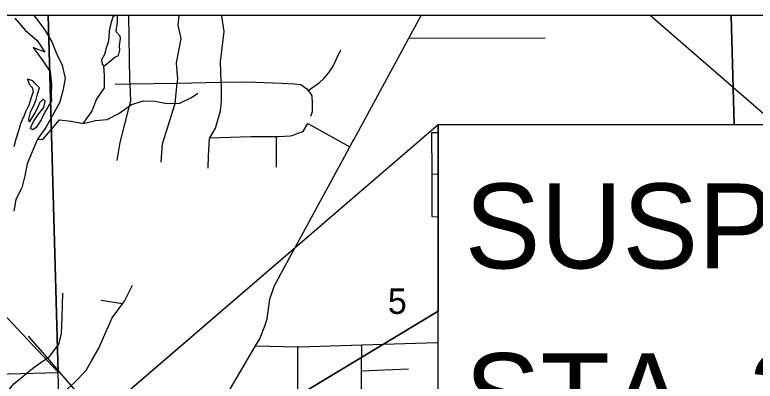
# Model space of a CAD drawing. Extents: x -37878.7 to -37844.7, y -19791.4 to -19769.4.
# Drawn here: x -37872.242 to -37871.021, y -19774.693 to -19774.089 of the extents above; entities that cross this region are included whole.
import ezdxf

# ---------------------------------------------------------------- set-up
doc = ezdxf.new("R2010")
doc.units = 0
for name, color, linetype in [('GM_X_City_Street', 7, 'Continuous'), ('GM_X_Major_River', 7, 'Continuous'), ('GM_X_Minor_Lake', 7, 'Continuous'), ('GM_X_Minor_River', 7, 'Continuous'), ('GM_X_Section', 7, 'Continuous'), ('GM_X_Section_Text', 7, 'Continuous'), ('GM_X_State_Route', 7, 'Continuous'), ('GM_X_US_Route', 7, 'Continuous'), ('TX_P_1', 7, 'Continuous')]:
    doc.layers.add(name, color=color, linetype=linetype)

msp = doc.modelspace()

# ---------------------------------------------------------------- linework, layer by layer
at = {"layer": 'GM_X_City_Street'}
for points in [[(-37872.0728, -19774.3288), (-37872.0683, -19774.299), (-37872.0607, -19774.2691), (-37872.0534, -19774.2411), (-37872.0504, -19774.2308), (-37872.0518, -19774.2025), (-37872.0521, -19774.1967), (-37872.0539, -19774.0898)], [(-37872.0003, -19774.3317), (-37871.9984, -19774.3013), (-37871.9774, -19774.2348), (-37871.9739, -19774.2012), (-37871.9733, -19774.1948), (-37871.975, -19774.1679), (-37871.9678, -19774.1279), (-37871.9726, -19774.1056), (-37871.9709, -19774.0898)], [(-37871.9228, -19774.3418), (-37871.9223, -19774.3213), (-37871.9209, -19774.2931), (-37871.9201, -19774.2917), (-37871.9108, -19774.2757), (-37871.9026, -19774.247), (-37871.9011, -19774.2317), (-37871.9012, -19774.2044), (-37871.9014, -19774.2), (-37871.9027, -19774.166), (-37871.8969, -19774.1161), (-37871.9004, -19774.0907), (-37871.9002, -19774.0898)], [(-37871.592, -19774.127), (-37871.3671, -19774.1266)], [(-37871.7581, -19774.2135), (-37871.7396, -19774.2001), (-37871.7318, -19774.1934), (-37871.7234, -19774.1833), (-37871.7169, -19774.1736), (-37871.7112, -19774.1613), (-37871.704, -19774.1462)], [(-37872.0763, -19774.2029), (-37872.0518, -19774.2025), (-37871.9739, -19774.2012), (-37871.9014, -19774.2), (-37871.8593, -19774.1993), (-37871.802, -19774.2013), (-37871.7804, -19774.2025), (-37871.7701, -19774.2034), (-37871.7601, -19774.2107), (-37871.7581, -19774.2135), (-37871.7539, -19774.2197)], [(-37871.7539, -19774.2197), (-37871.7522, -19774.2222), (-37871.7514, -19774.2351), (-37871.7517, -19774.2484), (-37871.7542, -19774.2561)], [(-37871.8164, -19774.2895), (-37871.816, -19774.2895), (-37871.8104, -19774.2896), (-37871.8077, -19774.2896), (-37871.7873, -19774.2882), (-37871.7831, -19774.2871), (-37871.7717, -19774.2829), (-37871.7681, -19774.2814), (-37871.766, -19774.28), (-37871.7587, -19774.268), (-37871.6894, -19774.3064)], [(-37871.9201, -19774.2917), (-37871.8524, -19774.2891), (-37871.8164, -19774.2895)], [(-37871.8104, -19774.3402), (-37871.8104, -19774.2896)], [(-37871.5548, -19774.283), (-37871.544, -19774.2828)], [(-37871.5548, -19774.283), (-37871.5544, -19774.3513), (-37871.5541, -19774.4216), (-37871.544, -19774.4217)], [(-37871.5544, -19774.3513), (-37871.544, -19774.3511)], [(-37872.1159, -19774.6604), (-37872.1039, -19774.6394), (-37872.0815, -19774.5884), (-37872.0642, -19774.5654), (-37872.061, -19774.5611), (-37872.048, -19774.5344)], [(-37872.3287, -19774.8159), (-37872.3022, -19774.7677), (-37872.2433, -19774.6974), (-37872.2097, -19774.6698), (-37872.1882, -19774.6547), (-37872.1847, -19774.6522), (-37872.1692, -19774.6318), (-37872.1649, -19774.615), (-37872.1639, -19774.5876), (-37872.1628, -19774.5477)], [(-37872.0642, -19774.5654), (-37872.0997, -19774.5598)], [(-37872.092, -19774.7656), (-37872.0938, -19774.7635), (-37872.1055, -19774.7499), (-37872.1489, -19774.7001), (-37872.1882, -19774.6547), (-37872.2195, -19774.6187)], [(-37871.8448, -19774.6347), (-37871.7749, -19774.6363), (-37871.7731, -19774.6364), (-37871.6698, -19774.633), (-37871.5455, -19774.6291), (-37871.5434, -19774.629)], [(-37871.6552, -19775.4518), (-37871.6539, -19775.3706), (-37871.6549, -19775.3071), (-37871.6549, -19775.2283), (-37871.6728, -19775.1244), (-37871.6721, -19775.0128), (-37871.6706, -19774.7769), (-37871.6703, -19774.7245), (-37871.67, -19774.6758), (-37871.6698, -19774.633)], [(-37871.7783, -19775.1244), (-37871.7783, -19775.1232), (-37871.7775, -19775.0138), (-37871.7769, -19774.9281), (-37871.7753, -19774.6945), (-37871.7749, -19774.6363)], [(-37872.2751, -19774.8469), (-37872.2473, -19774.8077), (-37872.209, -19774.7565), (-37872.1695, -19774.7182), (-37872.1489, -19774.7001), (-37872.1442, -19774.696), (-37872.1248, -19774.6762), (-37872.1159, -19774.6604), (-37872.1159, -19774.6604)], [(-37871.67, -19774.6758), (-37871.5924, -19774.6724)]]:
    msp.add_lwpolyline(points, dxfattribs=at)
at = {"layer": 'GM_X_Major_River'}
for points in [[(-37872.2105, -19774.0898), (-37872.2072, -19774.0936), (-37872.1931, -19774.1131), (-37872.1806, -19774.1333), (-37872.173, -19774.1525), (-37872.1639, -19774.1716), (-37872.1589, -19774.1939), (-37872.1626, -19774.2141), (-37872.1682, -19774.234), (-37872.1796, -19774.2547), (-37872.1909, -19774.2747), (-37872.2045, -19774.294), (-37872.2131, -19774.3146), (-37872.2214, -19774.3346), (-37872.2256, -19774.354), (-37872.2301, -19774.3738), (-37872.2403, -19774.3934), (-37872.2437, -19774.4128)], [(-37872.242, -19774.0944), (-37872.2246, -19774.1137), (-37872.2049, -19774.1311), (-37872.1924, -19774.1502), (-37872.2118, -19774.1427)], [(-37872.2118, -19774.1427), (-37872.1966, -19774.1628), (-37872.1833, -19774.1827), (-37872.1814, -19774.2028), (-37872.1821, -19774.2218), (-37872.1816, -19774.2308)], [(-37872.1816, -19774.2308), (-37872.1918, -19774.2481), (-37872.1984, -19774.2616), (-37872.2068, -19774.2747), (-37872.2124, -19774.2782), (-37872.2159, -19774.276), (-37872.2137, -19774.2702), (-37872.2097, -19774.263), (-37872.2031, -19774.2529), (-37872.1961, -19774.2441), (-37872.1942, -19774.2417), (-37872.1918, -19774.2311), (-37872.1953, -19774.2277), (-37872.2012, -19774.2339), (-37872.203, -19774.2385), (-37872.2085, -19774.2496), (-37872.2143, -19774.2593), (-37872.2184, -19774.2654), (-37872.2188, -19774.2605), (-37872.2157, -19774.2475), (-37872.2102, -19774.2372), (-37872.2066, -19774.2283), (-37872.2042, -19774.2196), (-37872.2014, -19774.2089), (-37872.2095, -19774.2007), (-37872.2122, -19774.1977), (-37872.221, -19774.1949), (-37872.2181, -19774.2028), (-37872.2135, -19774.2088), (-37872.2118, -19774.2159), (-37872.2143, -19774.2232), (-37872.2186, -19774.2377), (-37872.224, -19774.2485), (-37872.2269, -19774.2561), (-37872.2287, -19774.2592), (-37872.2323, -19774.2687), (-37872.2359, -19774.2798), (-37872.2401, -19774.2936), (-37872.2436, -19774.3062)]]:
    msp.add_lwpolyline(points, dxfattribs=at)
at = {"layer": 'GM_X_Minor_Lake'}
msp.add_line((-37872.0878, -19774.134), (-37872.0913, -19774.1435), dxfattribs=at)
msp.add_lwpolyline([(-37872.0913, -19774.1435), (-37872.0942, -19774.1542), (-37872.0989, -19774.1627), (-37872.098, -19774.1702), (-37872.0949, -19774.1732), (-37872.09, -19774.1697), (-37872.0833, -19774.1638), (-37872.077, -19774.1584), (-37872.0706, -19774.1556), (-37872.0689, -19774.1468), (-37872.0694, -19774.14), (-37872.0674, -19774.1278), (-37872.0683, -19774.124), (-37872.0741, -19774.117), (-37872.0749, -19774.1147), (-37872.0732, -19774.1056), (-37872.0726, -19774.0998), (-37872.0723, -19774.0941), (-37872.0724, -19774.0911), (-37872.0754, -19774.0893), (-37872.0803, -19774.092), (-37872.0838, -19774.105), (-37872.0862, -19774.1153), (-37872.0868, -19774.1267), (-37872.0878, -19774.134)], dxfattribs=at)
at = {"layer": 'GM_X_Minor_River'}
msp.add_line((-37872.2889, -19774.552), (-37872.1703, -19774.6781), dxfattribs=at)
for points in [[(-37872.1293, -19774.2681), (-37872.1149, -19774.248), (-37872.1074, -19774.2281), (-37872.0941, -19774.2089), (-37872.0942, -19774.1884), (-37872.0949, -19774.1732)], [(-37872.2045, -19774.294), (-37872.1954, -19774.2941), (-37872.1684, -19774.2621), (-37872.149, -19774.2643), (-37872.1293, -19774.2681), (-37872.1089, -19774.2627), (-37872.0896, -19774.2611), (-37872.0705, -19774.2513), (-37872.0496, -19774.2364), (-37872.0297, -19774.2303), (-37872.0107, -19774.231), (-37871.9913, -19774.2348), (-37871.9697, -19774.2343), (-37871.9506, -19774.2252), (-37871.9398, -19774.2181)]]:
    msp.add_lwpolyline(points, dxfattribs=at)
at = {"layer": 'GM_X_Section'}
for points in [[(-37872.1869, -19774.0898), (-37872.1703, -19774.6795), (-37872.5802, -19774.6904), (-37872.9663, -19774.7007), (-37873.2969, -19774.7059), (-37873.6902, -19774.7116), (-37873.7599, -19774.7127), (-37873.7756, -19774.0615), (-37873.0522, -19774.0492), (-37872.2676, -19774.0343)], [(-37871.041, -19774.8684), (-37871.0324, -19775.2124), (-37871.0355, -19775.2124), (-37872.1545, -19775.2374), (-37872.1703, -19774.6795), (-37872.1869, -19774.0898)], [(-37871.0604, -19774.0898), (-37871.0559, -19774.2693)], [(-37871.0559, -19774.2693), (-37871.0604, -19774.0898)]]:
    msp.add_lwpolyline(points, dxfattribs=at)
at = {"layer": 'GM_X_State_Route'}
for points in [[(-37871.6682, -19774.2672), (-37871.592, -19774.127), (-37871.5718, -19774.0898)], [(-37871.6825, -19774.2936), (-37871.6714, -19774.2732), (-37871.6682, -19774.2672)], [(-37871.7016, -19774.3288), (-37871.6894, -19774.3064), (-37871.6855, -19774.2992), (-37871.6825, -19774.2936)], [(-37871.8286, -19774.5983), (-37871.8256, -19774.5903), (-37871.8214, -19774.5579), (-37871.8136, -19774.5353), (-37871.7043, -19774.3338), (-37871.7016, -19774.3288)], [(-37872.3345, -19775.2871), (-37872.3238, -19775.2719), (-37872.2979, -19775.235), (-37872.2442, -19775.1584), (-37872.2162, -19775.1185), (-37872.1923, -19775.0845), (-37872.1826, -19775.0707), (-37872.142, -19775.0128), (-37872.1183, -19774.9791), (-37872.1077, -19774.9639), (-37872.1059, -19774.9619), (-37872.0907, -19774.944), (-37872.0144, -19774.8549), (-37871.9375, -19774.7717), (-37871.9152, -19774.7564), (-37871.8956, -19774.7213), (-37871.8486, -19774.6411), (-37871.8448, -19774.6347), (-37871.8377, -19774.6229), (-37871.8287, -19774.5987), (-37871.8286, -19774.5983)]]:
    msp.add_lwpolyline(points, dxfattribs=at)
at = {"layer": 'GM_X_US_Route'}
for points in [[(-37871.1937, -19774.0898), (-37871.119, -19774.1545)], [(-37871.119, -19774.1545), (-37870.9866, -19774.2693)]]:
    msp.add_lwpolyline(points, dxfattribs=at)
at = {"layer": 'TX_P_1'}
for p, q in [((-37870.2888, -19774.0898), (-37872.2676, -19774.0898)), ((-37872.7415, -19775.2998), (-37871.544, -19774.2693)), ((-37871.544, -19774.8684), (-37871.544, -19774.2693)), ((-37871.544, -19774.2693), (-37869.5652, -19774.2693)), ((-37872.7415, -19775.2998), (-37871.544, -19774.5775))]:
    msp.add_line(p, q, dxfattribs=at)
msp.add_lwpolyline([(-37872.7415, -19775.2998), (-37871.544, -19774.2693), (-37871.544, -19774.5775)], close=True, dxfattribs=at)

# ---------------------------------------------------------------- texts
at = {"layer": 'GM_X_Section_Text'}
msp.add_text('5', height=0.0419, rotation=0, dxfattribs=at).set_placement((-37871.6267, -19774.582))
at = {"layer": 'TX_P_1'}
for s, p in [('SUSPEND PROJECT', (-37871.5, -19774.5069)), ('STA. 25+00.00', (-37871.5, -19774.7869))]:
    msp.add_text(s, height=0.14, rotation=360, dxfattribs=at).set_placement(p)

doc.saveas('drawing.dxf')
